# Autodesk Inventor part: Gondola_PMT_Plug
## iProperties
Shininess: 64.0
Length Units: 11272
Angle Units: 11279
Time Units: 11290
Mass Units: 11286
Length Display Precision: 3
Angle Display Precision: 2
Compacted: True
Part Number: Gondola_PMT_Plug
Document SubType Name: Modeling
Created: 2004-08
Designer: John Blackburn
Manufacturer: Standard
Standards Organization: Custom
Material: Aluminum-6061-AHC
Density: 0.0
Volumn: 0.0
Area: 0.0
PropertySet Name: Model Information
Control State: 0
Master: False
Checked Out: False
Author: John Blackburn
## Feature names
1. Base1
